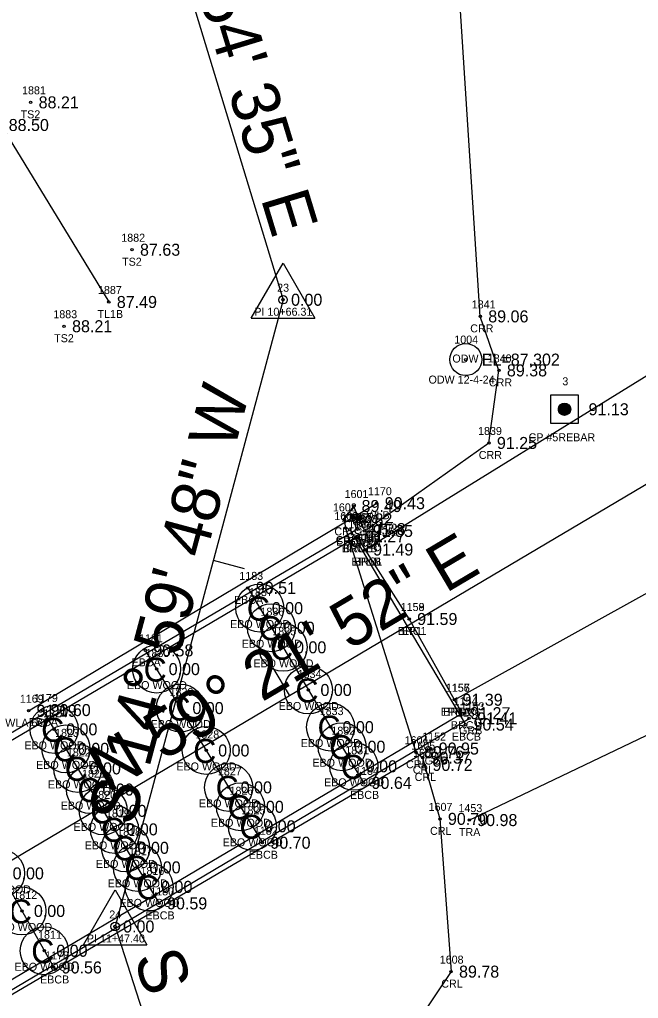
# Model space of a CAD drawing. Extents: x 2529517 to 2532038, y 935000 to 936944.
# Drawn here: x 2531126.5 to 2531203.8, y 935944.7 to 936067 of the extents above; entities that cross this region are included whole.
import ezdxf

# ---------------------------------------------------------------- set-up
doc = ezdxf.new("R2010")
doc.units = 0
for name, color, linetype in [('Default', 7, 'Continuous'), ('RD_DTM_BkLn_txCode', 7, 'Continuous'), ('RD_EX_Bridge', 7, 'Continuous'), ('RD_EX_Bridge_txCode', 7, 'Continuous'), ('RD_EX_GuardRail', 7, 'Continuous'), ('RD_EX_GuardRail_txCode', 7, 'Continuous'), ('RD_EX_H2O', 7, 'Continuous'), ('RD_EX_H2O_txCode', 7, 'Continuous'), ('RD_EX_Road', 7, 'Continuous'), ('RD_EX_Road_txCode', 7, 'Continuous'), ('RD_EX_TX_Bridge_ELEV', 7, 'Continuous'), ('RD_EX_TX_GuardRail_ELEV', 7, 'Continuous'), ('RD_EX_TX_H2O_ELEV', 7, 'Continuous'), ('RD_EX_TX_Misc_ELEV', 7, 'Continuous'), ('RD_EX_TX_Road_ELEV', 7, 'Continuous'), ('RD_EX_TX_UT_ELEV', 7, 'Continuous'), ('RD_EX_TX_VEG_ELEV', 7, 'Continuous'), ('RD_EX_UT', 7, 'Continuous'), ('RD_EX_UT_txCode', 7, 'Continuous'), ('RD_EX_VEG', 7, 'Continuous'), ('RD_EX_VEG_txCode', 7, 'Continuous'), ('RD_HC_Cl', 7, 'Continuous'), ('RD_HC_Data', 7, 'Continuous'), ('RD_HC_Data_Tic', 7, 'Continuous'), ('RD_HC_Survey', 7, 'Continuous'), ('RD_HC_Survey_ELEV', 7, 'Continuous'), ('RD_HC_Survey_txCode', 7, 'Continuous'), ('RD_HC_txCode', 7, 'Continuous'), ('RD_SMD_Locator', 7, 'Continuous')]:
    doc.layers.add(name, color=color, linetype=linetype)

msp = doc.modelspace()

# ---------------------------------------------------------------- linework, layer by layer
at = {"layer": 'Default'}
for p, q in [((2530557.05, 935625.34), (2531768.07, 936342.55)), ((2531140.11, 936095.44), (2531159.4, 936031.99)), ((2531159.4, 936031.99), (2531138.41, 935953.66)), ((2531138.41, 935953.66), (2531158.18, 935892.25))]:
    msp.add_line(p, q, dxfattribs=at)
at = {"layer": 'RD_EX_Bridge'}
for p, q in [((2531078.36, 935949.14), (2531168.64, 936002.42)), ((2531167.73, 936003.26), (2531182.2, 935978.9)), ((2531154.99, 935995.98), (2531169.46, 935971.61)), ((2531142.17, 935988.17), (2531156.81, 935964.13)), ((2531129.34, 935980.71), (2531143.9, 935956.55)), ((2531116.82, 935973.21), (2531130.73, 935948.54))]:
    msp.add_line(p, q, dxfattribs=at)
msp.add_lwpolyline([(2531078.36, 935949.14), (2531079.45, 935947.76), (2531084.76, 935938.51), (2531090.88, 935928.23), (2531091.53, 935927), (2531181.79, 935980.32), (2531180.82, 935982), (2531175.16, 935992.09), (2531169.65, 936000.77), (2531168.64, 936002.42)], dxfattribs=at)
for centre in [(2531156.49, 935993.45), (2531157.95, 935991), (2531159.4, 935988.55), (2531143.6, 935985.83), (2531162.57, 935983.22), (2531146.57, 935980.96), (2531165.33, 935978.58), (2531130.79, 935978.3), (2531166.78, 935976.13), (2531132.26, 935975.86), (2531149.79, 935975.66), (2531168.24, 935973.68), (2531133.73, 935973.42), (2531135.33, 935970.77), (2531152.6, 935971.05), (2531136.93, 935968.11), (2531154.08, 935968.62), (2531138.33, 935965.8), (2531155.56, 935966.18), (2531139.72, 935963.49), (2531124.1, 935960.3), (2531141.19, 935961.05), (2531142.66, 935958.61), (2531126.76, 935955.6), (2531129.56, 935950.63)]:
    msp.add_circle(centre, 3, dxfattribs=at)
at = {"layer": 'RD_EX_GuardRail'}
for p, q in [((2531168.7, 936003.32), (2531077.59, 935949.68)), ((2531090.96, 935925.3), (2531182.65, 935979.67))]:
    msp.add_line(p, q, dxfattribs=at)
at = {"layer": 'RD_EX_H2O'}
for points in [[(2531169.61, 936003.09), (2531185.12, 936014.09), (2531186.37, 936023.16), (2531184.04, 936029.91), (2531181.18, 936073.98), (2531171.96, 936106.16), (2531168.92, 936112.88), (2531161.58, 936114.63), (2531156.28, 936123.52), (2531154.46, 936124.24), (2531153.17, 936127.08), (2531152.81, 936126.44), (2531153.52, 936135.49)], [(2531169.61, 936003.09), (2531168.21, 936006.21), (2531167.04, 936004.54), (2531167.21, 936003.45), (2531176, 935975.44), (2531176.84, 935974.76), (2531177.07, 935973.85), (2531179, 935967.11), (2531180.39, 935948.02), (2531175.92, 935941.33), (2531173.5, 935933.2), (2531181.71, 935892.9), (2531201.16, 935775.97), (2531215.24, 935672.42), (2531231.54, 935569.22), (2531229.65, 935447.9)]]:
    msp.add_lwpolyline(points, dxfattribs=at)
for radius in [2, 0.15]:
    msp.add_circle((2531182.23, 936024.51), radius, dxfattribs=at)
at = {"layer": 'RD_EX_Road'}
for points in [[(2531169.65, 936000.77), (2531208.79, 936024.95), (2531292.04, 936074.02), (2531376.24, 936123.7), (2531460.37, 936174.49), (2531542.92, 936223.44), (2531626.67, 936270.85), (2531672.4, 936298.39), (2531714.28, 936327.21), (2531747.19, 936360.45), (2531761.42, 936377.32), (2531773.11, 936411.11), (2531782.2, 936441.65), (2531803.17, 936514.76), (2531820.28, 936585.8)], [(2531180.82, 935982), (2531220.82, 936004.21), (2531303.54, 936053.39), (2531388.75, 936103.71), (2531472.27, 936152.98), (2531554.79, 936201.9), (2531638.11, 936250.92), (2531683.19, 936278.28), (2531730.37, 936304.55), (2531771.5, 936341.26), (2531788.67, 936375.53), (2531805.57, 936434.84), (2531825.53, 936508.74), (2531844.13, 936579.65)], [(2531180.82, 935982), (2531175.16, 935992.09), (2531169.65, 936000.77)]]:
    msp.add_lwpolyline(points, dxfattribs=at)
at = {"layer": 'RD_EX_UT'}
for p, q in [((2531127.59, 935980.62), (2531171.11, 936006.56)), ((2531093.84, 935926.63), (2531177.85, 935975.9))]:
    msp.add_line(p, q, dxfattribs=at)
at = {"layer": 'RD_EX_VEG'}
msp.add_line((2531124.11, 936053.83), (2531137.62, 936031.71), dxfattribs=at)
msp.add_lwpolyline([(2531182.66, 935966.96), (2531230.8, 935989.97), (2531274.81, 936012.6), (2531313.69, 936036.35), (2531483.89, 936140.08), (2531501.35, 936141.05), (2531534.81, 936162.87), (2531566.74, 936177.64), (2531596.77, 936200.59), (2531599.53, 936176.46), (2531629.05, 936127.23), (2531618.55, 936099.22)], dxfattribs=at)
at = {"layer": 'RD_HC_Cl'}
for p, q in [((2530557.05, 935625.34), (2531768.07, 936342.55)), ((2531140.11, 936095.44), (2531159.4, 936031.99)), ((2531159.4, 936031.99), (2531138.41, 935953.66)), ((2531138.41, 935953.66), (2531158.18, 935892.25))]:
    msp.add_line(p, q, dxfattribs=at)
at = {"layer": 'RD_HC_Data'}
for p, q in [((2531155.43, 936029.7), (2531159.4, 936036.58)), ((2531159.4, 936036.58), (2531163.37, 936029.7)), ((2531155.43, 936029.7), (2531163.37, 936029.7)), ((2531134.44, 935951.37), (2531138.41, 935958.25)), ((2531138.41, 935958.25), (2531142.38, 935951.37)), ((2531134.44, 935951.37), (2531142.38, 935951.37))]:
    msp.add_line(p, q, dxfattribs=at)
for centre in [(2531159.4, 936031.99), (2531138.41, 935953.66)]:
    msp.add_circle(centre, 0.529, dxfattribs=at)
at = {"layer": 'RD_HC_Data_Tic'}
for p, q in [((2531150.68, 935999.45), (2531154.54, 935998.41)), ((2531160.2, 935982.55), (2531158.16, 935985.99))]:
    msp.add_line(p, q, dxfattribs=at)
at = {"layer": 'RD_HC_Survey'}
for p, q in [((2531193.83, 936018.12), (2531193.83, 936018.48)), ((2531193.86, 936018.04), (2531193.86, 936018.56)), ((2531193.88, 936017.98), (2531193.88, 936018.62)), ((2531193.91, 936017.93), (2531193.91, 936018.67)), ((2531193.93, 936017.89), (2531193.93, 936018.72)), ((2531193.96, 936017.85), (2531193.96, 936018.75)), ((2531193.98, 936017.82), (2531193.98, 936018.78)), ((2531194, 936017.79), (2531194, 936018.81)), ((2531194.03, 936017.76), (2531194.03, 936018.84)), ((2531194.05, 936017.74), (2531194.05, 936018.86)), ((2531194.08, 936017.72), (2531194.08, 936018.89)), ((2531194.1, 936017.7), (2531194.1, 936018.91)), ((2531194.13, 936017.68), (2531194.13, 936018.93)), ((2531194.15, 936017.66), (2531194.15, 936018.94)), ((2531194.18, 936017.65), (2531194.18, 936018.96)), ((2531194.2, 936017.63), (2531194.2, 936018.97)), ((2531194.23, 936017.62), (2531194.23, 936018.99)), ((2531194.25, 936017.61), (2531194.25, 936019)), ((2531194.28, 936017.6), (2531194.28, 936019.01)), ((2531194.3, 936017.59), (2531194.3, 936019.02)), ((2531194.33, 936017.58), (2531194.33, 936019.03)), ((2531194.35, 936017.57), (2531194.35, 936019.04)), ((2531194.38, 936017.56), (2531194.38, 936019.04)), ((2531194.4, 936017.55), (2531194.4, 936019.05)), ((2531194.43, 936017.55), (2531194.43, 936019.06)), ((2531194.45, 936017.54), (2531194.45, 936019.06)), ((2531194.48, 936017.54), (2531194.48, 936019.06)), ((2531194.5, 936017.54), (2531194.5, 936019.07)), ((2531194.52, 936017.54), (2531194.52, 936019.07)), ((2531194.55, 936017.53), (2531194.55, 936019.07)), ((2531194.57, 936017.53), (2531194.57, 936019.07)), ((2531194.6, 936017.53), (2531194.6, 936019.07)), ((2531194.62, 936017.53), (2531194.62, 936019.07)), ((2531194.65, 936017.54), (2531194.65, 936019.07)), ((2531194.67, 936017.54), (2531194.67, 936019.07)), ((2531194.7, 936017.54), (2531194.7, 936019.06)), ((2531194.72, 936017.55), (2531194.72, 936019.06)), ((2531194.75, 936017.55), (2531194.75, 936019.05)), ((2531194.77, 936017.56), (2531194.77, 936019.05)), ((2531194.8, 936017.56), (2531194.8, 936019.04)), ((2531194.82, 936017.57), (2531194.82, 936019.03)), ((2531194.85, 936017.58), (2531194.85, 936019.02)), ((2531194.87, 936017.59), (2531194.87, 936019.01)), ((2531194.9, 936017.6), (2531194.9, 936019)), ((2531194.92, 936017.61), (2531194.92, 936018.99)), ((2531194.95, 936017.63), (2531194.95, 936018.98)), ((2531194.97, 936017.64), (2531194.97, 936018.97)), ((2531194.99, 936017.65), (2531194.99, 936018.95)), ((2531195.02, 936017.67), (2531195.02, 936018.93)), ((2531195.04, 936017.69), (2531195.04, 936018.92)), ((2531195.07, 936017.71), (2531195.07, 936018.9)), ((2531195.09, 936017.73), (2531195.09, 936018.88)), ((2531195.12, 936017.75), (2531195.12, 936018.85)), ((2531195.14, 936017.78), (2531195.14, 936018.83)), ((2531195.17, 936017.81), (2531195.17, 936018.8)), ((2531195.19, 936017.84), (2531195.19, 936018.77)), ((2531195.22, 936017.87), (2531195.22, 936018.73)), ((2531195.24, 936017.91), (2531195.24, 936018.69)), ((2531195.27, 936017.96), (2531195.27, 936018.65)), ((2531195.29, 936018.01), (2531195.29, 936018.59)), ((2531195.32, 936018.08), (2531195.32, 936018.53)), ((2531195.34, 936018.19), (2531195.34, 936018.41))]:
    msp.add_line(p, q, dxfattribs=at)
msp.add_lwpolyline([(2531196.33, 936020.05), (2531192.83, 936020.05), (2531192.83, 936016.55), (2531196.33, 936016.55)], close=True, dxfattribs=at)
msp.add_circle((2531194.58, 936018.3), 0.769, dxfattribs=at)
at = {"layer": 'RD_SMD_Locator'}
for centre in [(2531127.85, 936056.66), (2531140.52, 936038.24), (2531137.62, 936031.71), (2531159.4, 936031.99), (2531184.04, 936029.91), (2531132.03, 936028.68), (2531186.37, 936023.16), (2531194.58, 936018.3), (2531185.12, 936014.09), (2531168.21, 936006.21), (2531171.11, 936006.56), (2531167.04, 936004.54), (2531167.21, 936003.45), (2531167.73, 936003.26), (2531168.64, 936002.42), (2531168.64, 936002.42), (2531168.7, 936003.32), (2531169.61, 936003.09), (2531169.61, 936003.09), (2531169.65, 936000.77), (2531169.65, 936000.77), (2531169.65, 936000.77), (2531154.99, 935995.98), (2531156.49, 935993.45), (2531175.16, 935992.09), (2531175.16, 935992.09), (2531157.95, 935991), (2531142.17, 935988.17), (2531159.4, 935988.55), (2531143.6, 935985.83), (2531162.57, 935983.22), (2531180.82, 935982), (2531180.82, 935982), (2531180.82, 935982), (2531127.59, 935980.62), (2531129.34, 935980.71), (2531146.57, 935980.96), (2531181.79, 935980.32), (2531182.2, 935978.9), (2531182.65, 935979.67), (2531130.79, 935978.3), (2531165.33, 935978.58), (2531132.26, 935975.86), (2531149.79, 935975.66), (2531166.78, 935976.13), (2531176, 935975.44), (2531177.85, 935975.9), (2531176.84, 935974.76), (2531133.73, 935973.42), (2531168.24, 935973.68), (2531177.07, 935973.85), (2531169.46, 935971.61), (2531135.33, 935970.77), (2531152.6, 935971.05), (2531136.93, 935968.11), (2531154.08, 935968.62), (2531179, 935967.11), (2531182.66, 935966.96), (2531138.33, 935965.8), (2531155.56, 935966.18), (2531139.72, 935963.49), (2531156.81, 935964.13), (2531141.19, 935961.05), (2531142.66, 935958.61), (2531143.9, 935956.55), (2531126.76, 935955.6), (2531138.41, 935953.66), (2531129.56, 935950.63), (2531130.73, 935948.54), (2531180.39, 935948.02)]:
    msp.add_circle(centre, 0.15, dxfattribs=at)

# ---------------------------------------------------------------- texts
at = {"layer": 'RD_DTM_BkLn_txCode'}
for s, p in [('1881', (2531126.78, 936057.66)), ('TS2', (2531126.6, 936054.66)), ('1882', (2531139.18, 936039.24)), ('TS2', (2531139.28, 936036.24)), ('1883', (2531130.69, 936029.68)), ('TS2', (2531130.79, 936026.68))]:
    msp.add_text(s, height=1, dxfattribs=at).set_placement(p)
at = {"layer": 'RD_EX_Bridge'}
for p in [(2531154.86, 935991.89), (2531156.32, 935989.44), (2531157.77, 935986.99), (2531141.97, 935984.27), (2531160.94, 935981.66), (2531144.94, 935979.4), (2531129.16, 935976.74), (2531163.7, 935977.02), (2531130.63, 935974.3), (2531148.16, 935974.1), (2531165.15, 935974.57), (2531132.1, 935971.86), (2531166.61, 935972.11), (2531133.7, 935969.21), (2531150.97, 935969.49), (2531135.3, 935966.55), (2531152.45, 935967.06), (2531136.7, 935964.24), (2531153.93, 935964.62), (2531138.09, 935961.93), (2531139.56, 935959.49), (2531141.03, 935957.05), (2531125.12, 935954.04), (2531127.92, 935949.07)]:
    msp.add_text('C', height=3, dxfattribs=at).set_placement(p)
at = {"layer": 'RD_EX_Bridge_txCode'}
for s, p in [('1185', (2531166.66, 936004.26)), ('1163', (2531167.56, 936003.42)), ('1164', (2531167.56, 936003.42)), ('1160', (2531168.52, 936001.77)), ('EBCA', (2531166.01, 936001.26)), ('BRC1B', (2531166.75, 936000.42)), ('BRCB', (2531166.92, 936000.42)), ('BRC1', (2531168.23, 935998.77)), ('1183', (2531153.93, 935996.98)), ('EBCA', (2531153.27, 935993.98)), ('1837', (2531155.15, 935994.95)), ('1159', (2531174.1, 935993.09)), ('1836', (2531156.58, 935992.5)), ('EBO WOOD', (2531152.78, 935990.95)), ('1181', (2531141.39, 935989.17)), ('1835', (2531158.06, 935990.05)), ('BRC1', (2531173.75, 935990.09)), ('EBO WOOD', (2531154.23, 935988.5)), ('1830', (2531142.21, 935987.33)), ('EBCA', (2531140.46, 935986.17)), ('EBO WOOD', (2531155.69, 935986.05)), ('1834', (2531161.22, 935984.72)), ('EBO WOOD', (2531139.88, 935983.33)), ('1155', (2531179.76, 935983)), ('1179', (2531128.27, 935981.71)), ('1829', (2531145.22, 935982.46)), ('EBO WOOD', (2531158.85, 935980.72)), ('1154', (2531180.72, 935981.32)), ('1824', (2531129.44, 935979.8)), ('1833', (2531163.98, 935980.08)), ('BRC1', (2531179.41, 935980)), ('1186', (2531181.11, 935979.9)), ('EBCA', (2531127.62, 935978.71)), ('EBO WOOD', (2531142.85, 935978.46)), ('BRC1', (2531180.37, 935978.32)), ('1823', (2531130.91, 935977.36)), ('1828', (2531148.44, 935977.16)), ('1832', (2531165.44, 935977.63)), ('EBCB', (2531180.49, 935976.9)), ('EBO WOOD', (2531127.07, 935975.8)), ('EBO WOOD', (2531161.61, 935976.08)), ('1822', (2531132.38, 935974.92)), ('1831', (2531167.17, 935975.18)), ('EBO WOOD', (2531128.54, 935973.36)), ('EBO WOOD', (2531146.07, 935973.16)), ('EBO WOOD', (2531163.07, 935973.63)), ('1821', (2531134.27, 935972.27)), ('1827', (2531151.25, 935972.55)), ('1184', (2531168.4, 935972.61)), ('EBO WOOD', (2531130.01, 935970.92)), ('EBO WOOD', (2531164.52, 935971.18)), ('1820', (2531135.55, 935969.61)), ('1826', (2531152.71, 935970.12)), ('EBCB', (2531167.76, 935969.61)), ('EBO WOOD', (2531131.61, 935968.27)), ('EBO WOOD', (2531148.88, 935968.55)), ('1819', (2531137.26, 935967.3)), ('1825', (2531154.22, 935967.68)), ('EBO WOOD', (2531150.37, 935966.12)), ('EBO WOOD', (2531133.22, 935965.61)), ('1818', (2531138.66, 935964.99)), ('1182', (2531155.75, 935965.13)), ('EBO WOOD', (2531151.85, 935963.68)), ('EBO WOOD', (2531134.61, 935963.3)), ('1817', (2531140.13, 935962.55)), ('EBCB', (2531155.11, 935962.13)), ('EBO WOOD', (2531136, 935960.99)), ('1816', (2531141.58, 935960.11)), ('EBO WOOD', (2531137.48, 935958.55)), ('EBO WOOD', (2531120.39, 935957.8)), ('1180', (2531142.8, 935957.55)), ('1812', (2531125.69, 935957.1)), ('EBO WOOD', (2531138.95, 935956.11)), ('EBCB', (2531142.2, 935954.55)), ('EBO WOOD', (2531123.04, 935953.1)), ('1811', (2531128.78, 935952.13)), ('1178', (2531129.67, 935949.54)), ('EBO WOOD', (2531125.84, 935948.13)), ('EBCB', (2531129.03, 935946.54))]:
    msp.add_text(s, height=1, dxfattribs=at).set_placement(p)
at = {"layer": 'RD_EX_GuardRail_txCode'}
for s, p in [('1165', (2531167.61, 936004.32)), ('GRA', (2531167.43, 936001.32)), ('1153', (2531181.59, 935980.67)), ('GRB', (2531181.4, 935977.67))]:
    msp.add_text(s, height=1, dxfattribs=at).set_placement(p)
at = {"layer": 'RD_EX_H2O'}
msp.add_text('ODW', height=1, dxfattribs=at).set_placement((2531180.56, 936024.14))
at = {"layer": 'RD_EX_H2O_txCode'}
for s, p in [('1841', (2531182.98, 936030.91)), ('CRR', (2531182.79, 936027.91)), ('1004', (2531180.8, 936026.51)), ('1840', (2531184.98, 936024.16)), ('ODW 12-4-24', (2531177.58, 936021.51)), ('CRR', (2531185.12, 936021.16)), ('1839', (2531183.77, 936015.09)), ('CRR', (2531183.86, 936012.09)), ('1601', (2531167.09, 936007.21)), ('1602', (2531165.63, 936005.54)), ('1603', (2531165.8, 936004.45)), ('CRL', (2531166.98, 936004.21)), ('1600', (2531168.16, 936004.09)), ('1838', (2531168.26, 936004.09)), ('CRL', (2531165.81, 936002.54)), ('CRL', (2531165.98, 936001.45)), ('CRRA', (2531167.87, 936001.09)), ('CRLA', (2531167.89, 936001.09)), ('1604', (2531174.59, 935976.44)), ('1605', (2531175.43, 935975.76)), ('1606', (2531175.64, 935974.85)), ('CRL', (2531174.77, 935973.44)), ('CRL', (2531175.61, 935972.76)), ('CRL', (2531175.84, 935971.85)), ('1607', (2531177.59, 935968.11)), ('CRL', (2531177.77, 935965.11)), ('1608', (2531178.98, 935949.02)), ('CRL', (2531179.17, 935946.02))]:
    msp.add_text(s, height=1, dxfattribs=at).set_placement(p)
at = {"layer": 'RD_EX_Road_txCode'}
for s, p in [('1162', (2531168.56, 936001.77)), ('1161', (2531168.84, 936001.77)), ('EPLA', (2531167.96, 935998.77)), ('EP1B', (2531168.25, 935998.77)), ('1158', (2531174.1, 935993.09)), ('EP1', (2531174.24, 935990.09)), ('1156', (2531179.74, 935983)), ('1157', (2531179.76, 935983)), ('EPRA', (2531179.11, 935980)), ('EP1A', (2531179.41, 935980))]:
    msp.add_text(s, height=1, dxfattribs=at).set_placement(p)
at = {"layer": 'RD_EX_TX_Bridge_ELEV'}
for s, p in [('90.58', (2531168.73, 936002.51)), ('91.27', (2531169.64, 936001.67)), ('91.27', (2531169.64, 936001.67)), ('91.49', (2531170.65, 936000.02)), ('90.51', (2531155.99, 935995.23)), ('0.00', (2531157.99, 935992.7)), ('91.59', (2531176.16, 935991.34)), ('0.00', (2531159.45, 935990.25)), ('90.58', (2531143.17, 935987.42)), ('0.00', (2531160.9, 935987.8)), ('0.00', (2531145.1, 935985.08)), ('0.00', (2531164.07, 935982.47)), ('91.39', (2531181.82, 935981.25)), ('90.60', (2531130.34, 935979.96)), ('0.00', (2531148.07, 935980.21)), ('91.27', (2531182.79, 935979.57)), ('0.00', (2531132.29, 935977.55)), ('0.00', (2531166.83, 935977.83)), ('90.54', (2531183.2, 935978.15)), ('0.00', (2531133.76, 935975.11)), ('0.00', (2531168.28, 935975.38)), ('0.00', (2531151.29, 935974.91)), ('0.00', (2531135.23, 935972.67)), ('0.00', (2531169.74, 935972.93)), ('0.00', (2531154.1, 935970.3)), ('90.64', (2531170.46, 935970.86)), ('0.00', (2531136.83, 935970.02)), ('0.00', (2531155.58, 935967.87)), ('0.00', (2531138.43, 935967.36)), ('0.00', (2531157.06, 935965.43)), ('0.00', (2531139.83, 935965.05)), ('90.70', (2531157.81, 935963.38)), ('0.00', (2531141.22, 935962.74)), ('0.00', (2531125.6, 935959.55)), ('0.00', (2531142.69, 935960.3)), ('0.00', (2531144.16, 935957.86)), ('90.59', (2531144.9, 935955.8)), ('0.00', (2531128.26, 935954.85)), ('0.00', (2531131.06, 935949.88)), ('90.56', (2531131.73, 935947.79))]:
    msp.add_text(s, height=1.5, dxfattribs=at).set_placement(p)
at = {"layer": 'RD_EX_TX_GuardRail_ELEV'}
for s, p in [('91.18', (2531169.7, 936002.57)), ('91.41', (2531183.65, 935978.92))]:
    msp.add_text(s, height=1.5, dxfattribs=at).set_placement(p)
at = {"layer": 'RD_EX_TX_H2O_ELEV'}
for s, p in [('89.06', (2531185.04, 936029.16)), ('EL=87.302', (2531184.23, 936023.76)), ('89.38', (2531187.37, 936022.41)), ('91.25', (2531186.12, 936013.34)), ('89.49', (2531169.21, 936005.46)), ('87.82', (2531168.04, 936003.79)), ('88.17', (2531168.21, 936002.7)), ('91.35', (2531170.61, 936002.34)), ('91.35', (2531170.61, 936002.34)), ('89.76', (2531177, 935974.69)), ('90.37', (2531177.84, 935974.01)), ('90.72', (2531178.07, 935973.1)), ('90.70', (2531180, 935966.36)), ('89.78', (2531181.39, 935947.27))]:
    msp.add_text(s, height=1.5, dxfattribs=at).set_placement(p)
at = {"layer": 'RD_EX_TX_Misc_ELEV'}
for s, p in [('88.21', (2531128.85, 936055.91)), ('87.63', (2531141.52, 936037.49)), ('88.21', (2531133.03, 936027.93))]:
    msp.add_text(s, height=1.5, dxfattribs=at).set_placement(p)
at = {"layer": 'RD_EX_TX_Road_ELEV'}
for s, p in [('91.49', (2531170.65, 936000.02)), ('91.49', (2531170.65, 936000.02)), ('91.59', (2531176.16, 935991.34)), ('91.39', (2531181.82, 935981.25)), ('91.39', (2531181.82, 935981.25))]:
    msp.add_text(s, height=1.5, dxfattribs=at).set_placement(p)
at = {"layer": 'RD_EX_TX_UT_ELEV'}
for s, p in [('90.43', (2531172.11, 936005.81)), ('91.19', (2531128.59, 935979.87)), ('90.95', (2531178.85, 935975.15))]:
    msp.add_text(s, height=1.5, dxfattribs=at).set_placement(p)
at = {"layer": 'RD_EX_TX_VEG_ELEV'}
for s, p in [('88.50', (2531125.11, 936053.08)), ('87.49', (2531138.62, 936030.96)), ('90.98', (2531183.66, 935966.21))]:
    msp.add_text(s, height=1.5, dxfattribs=at).set_placement(p)
at = {"layer": 'RD_EX_UT_txCode'}
for s, p in [('1170', (2531170.01, 936007.56)), ('WLB', (2531169.82, 936004.56)), ('1169', (2531126.5, 935981.62)), ('WLA 6CI', (2531124.68, 935978.62)), ('1152', (2531176.79, 935976.9)), ('UGCB', (2531176.12, 935973.9))]:
    msp.add_text(s, height=1, dxfattribs=at).set_placement(p)
at = {"layer": 'RD_EX_VEG_txCode'}
for s, p in [('1887', (2531136.27, 936032.71)), ('TL1B', (2531136.21, 936029.71)), ('1453', (2531181.32, 935967.96)), ('TRA', (2531181.38, 935964.96))]:
    msp.add_text(s, height=1, dxfattribs=at).set_placement(p)
at = {"layer": 'RD_HC_Data'}
for s, rotation, p in [('S 16%%d 54\' 35" E', 286.9097, (2531142.44, 936091.19)), ('S 14%%d 59\' 48" W', 75.0032, (2531140.69, 935966.05)), ('N 59%%d 21\' 52" E', 30.6357, (2531137.48, 935970.25)), ('S 17%%d 50\' 44" E', 287.8455, (2531140.71, 935949.77))]:
    msp.add_text(s, height=6, rotation=rotation, dxfattribs=at).set_placement(p)
at = {"layer": 'RD_HC_Survey_ELEV'}
for s, p in [('0.00', (2531160.4, 936031.24)), ('91.13', (2531197.58, 936017.55)), ('0.00', (2531139.41, 935952.91))]:
    msp.add_text(s, height=1.5, dxfattribs=at).set_placement(p)
at = {"layer": 'RD_HC_Survey_txCode'}
for s, p in [('3', (2531194.3, 936021.3)), ('CP #5REBAR', (2531190.08, 936014.3))]:
    msp.add_text(s, height=1, dxfattribs=at).set_placement(p)
at = {"layer": 'RD_HC_txCode'}
for s, p in [('23', (2531158.66, 936032.99)), ('PI 10+66.31', (2531155.81, 936029.99)), ('24', (2531137.68, 935954.66)), ('PI 11+47.40', (2531134.88, 935951.66))]:
    msp.add_text(s, height=1, dxfattribs=at).set_placement(p)

doc.saveas('drawing.dxf')
